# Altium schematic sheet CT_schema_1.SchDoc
size 849 x 820 mm
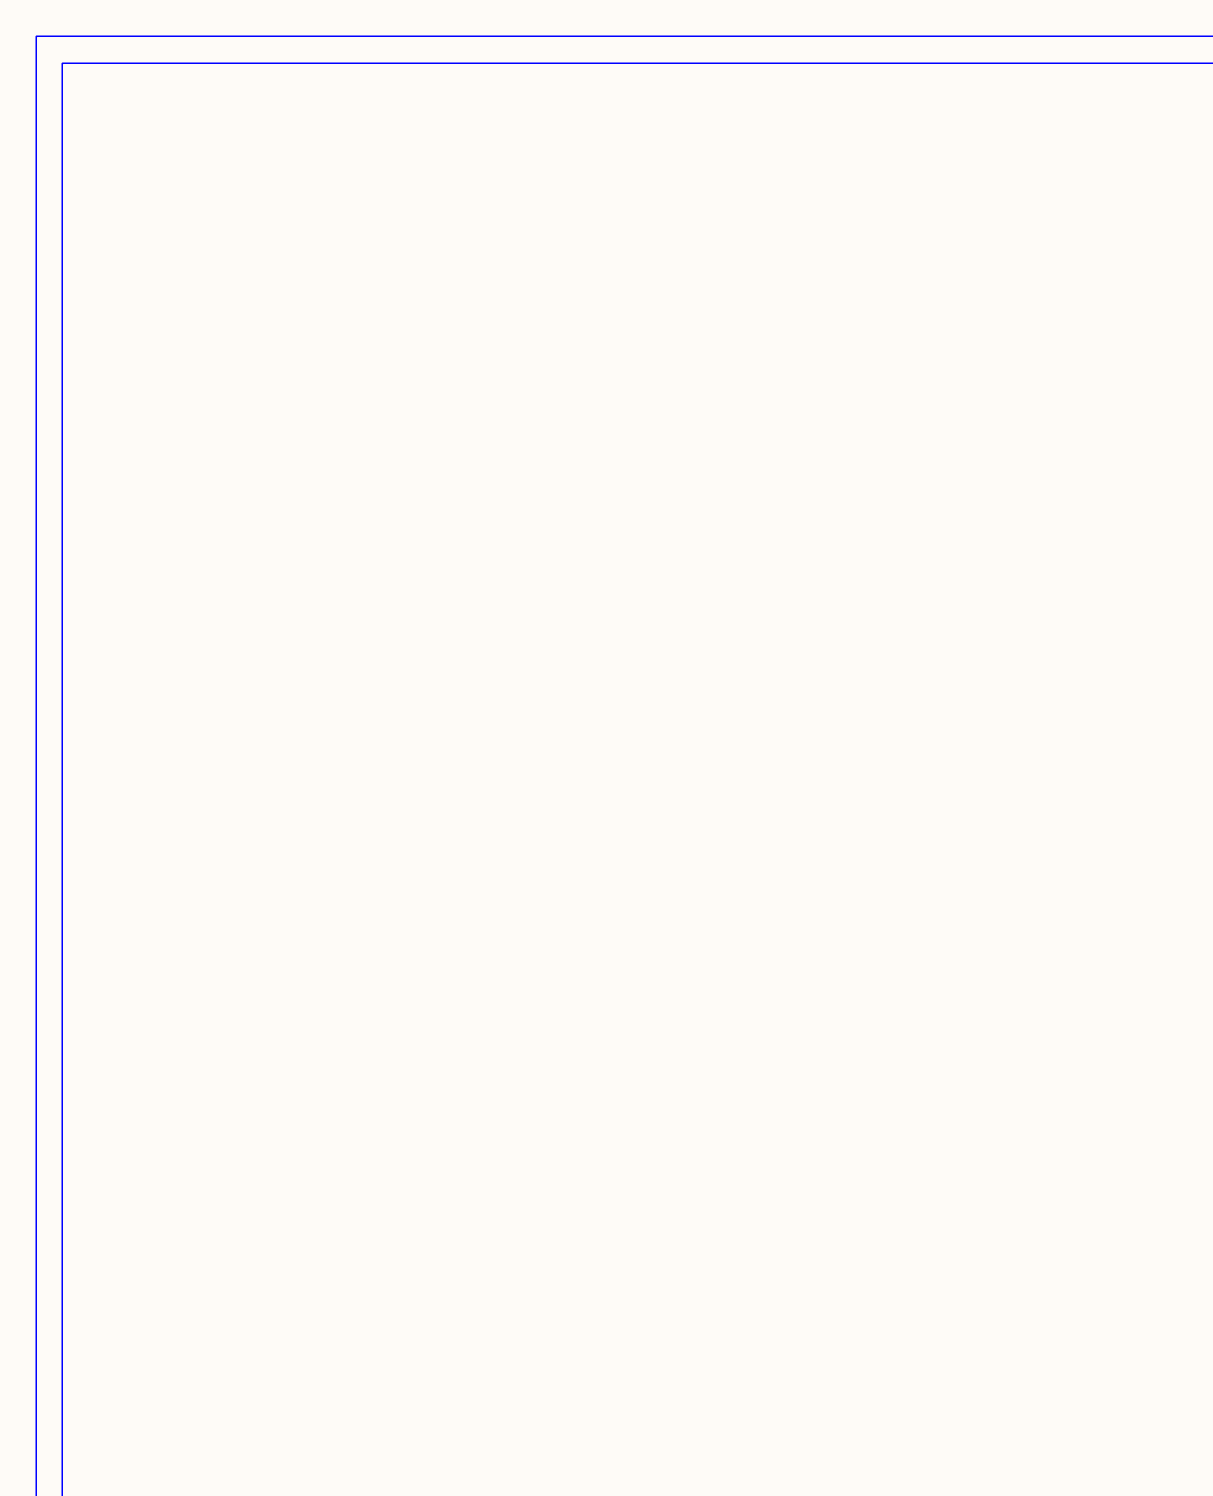
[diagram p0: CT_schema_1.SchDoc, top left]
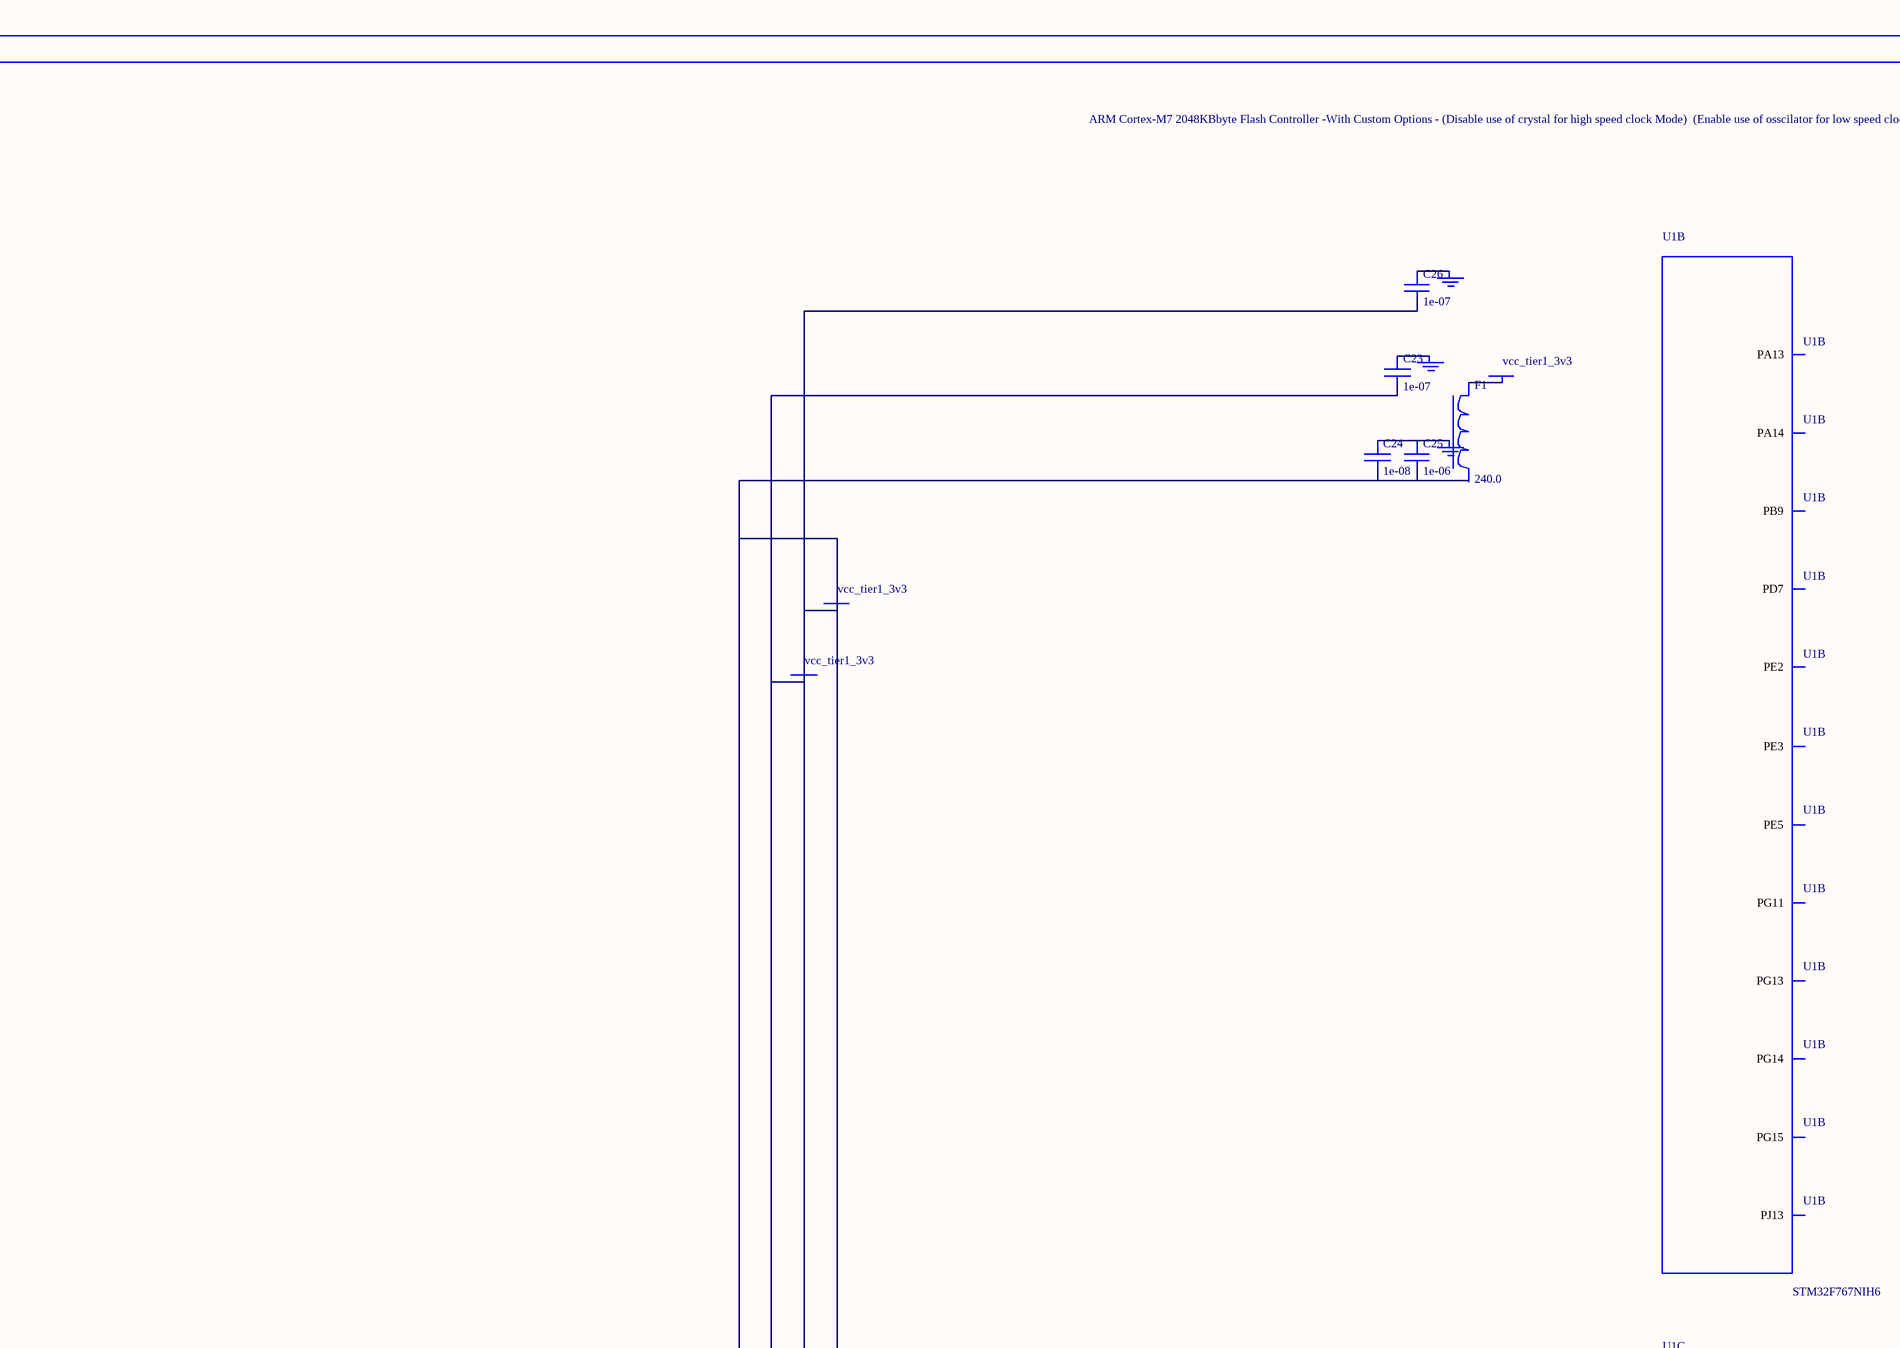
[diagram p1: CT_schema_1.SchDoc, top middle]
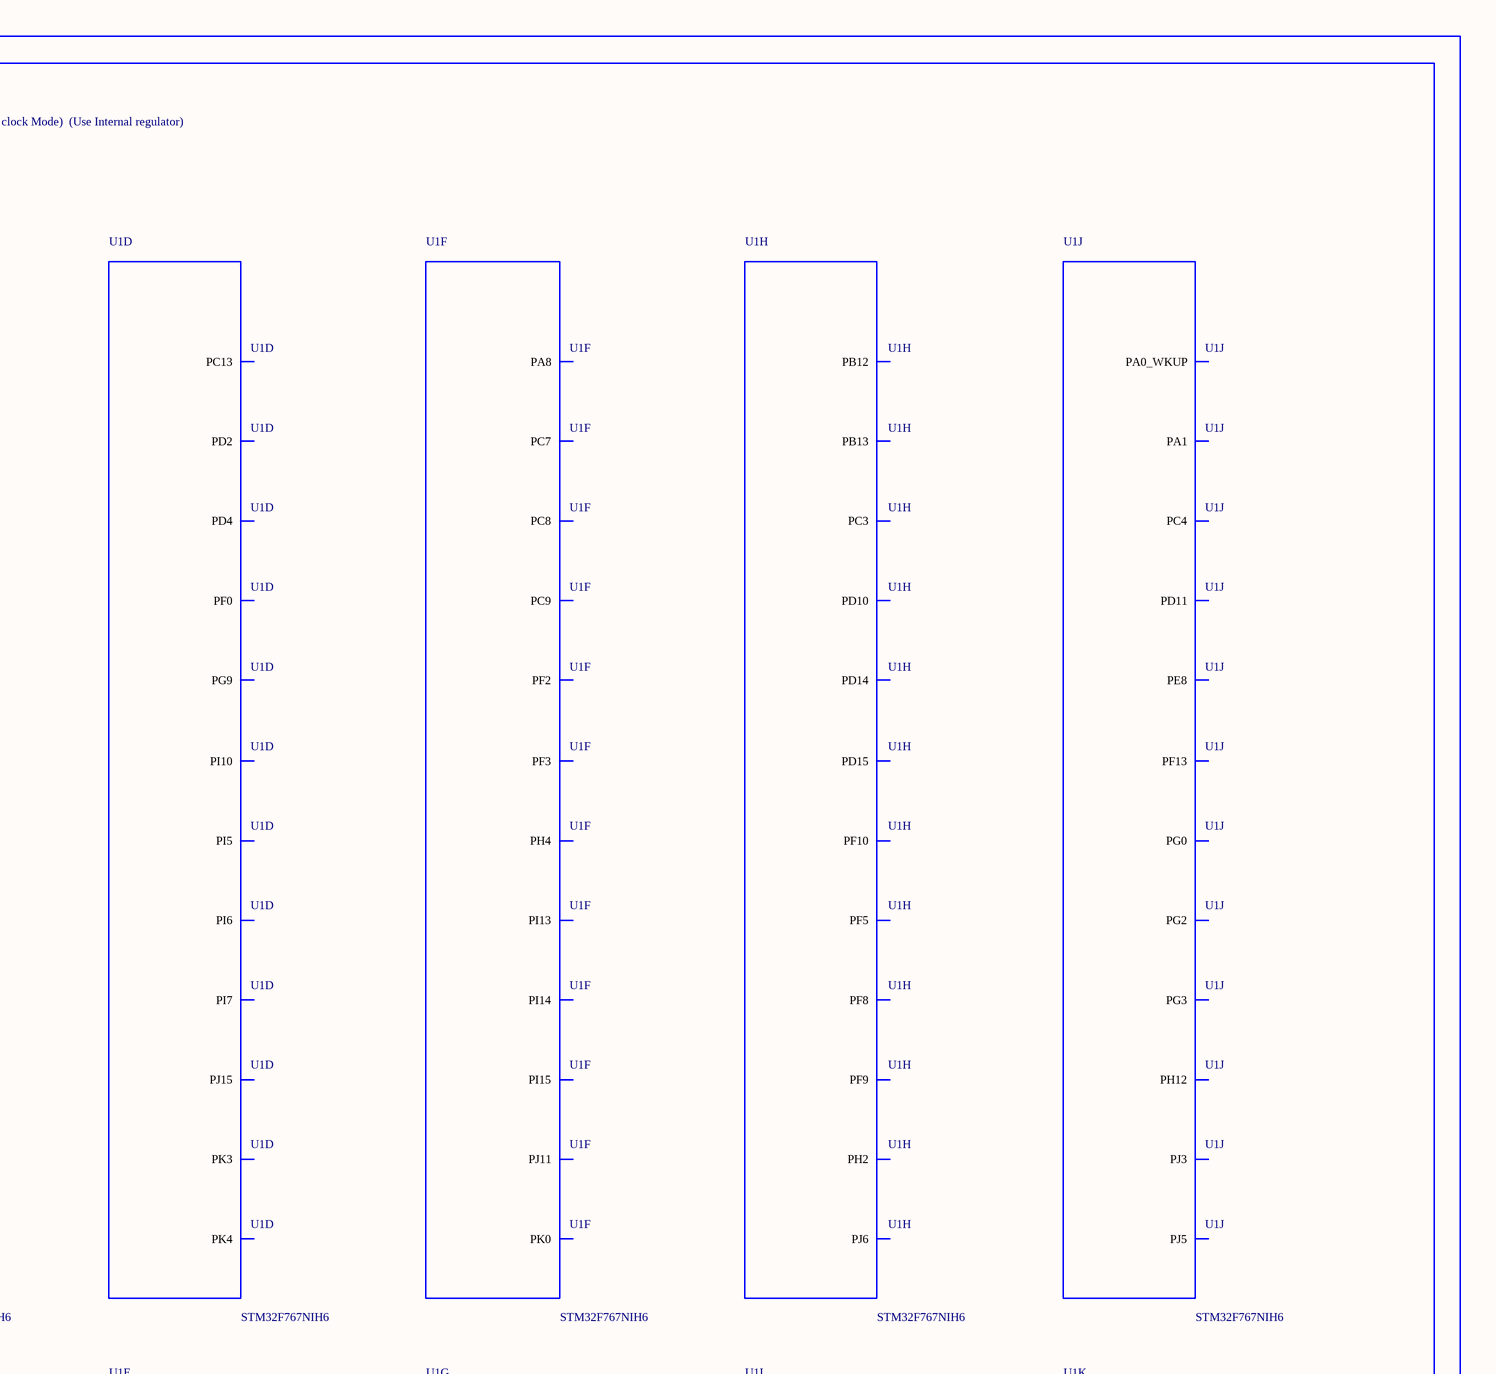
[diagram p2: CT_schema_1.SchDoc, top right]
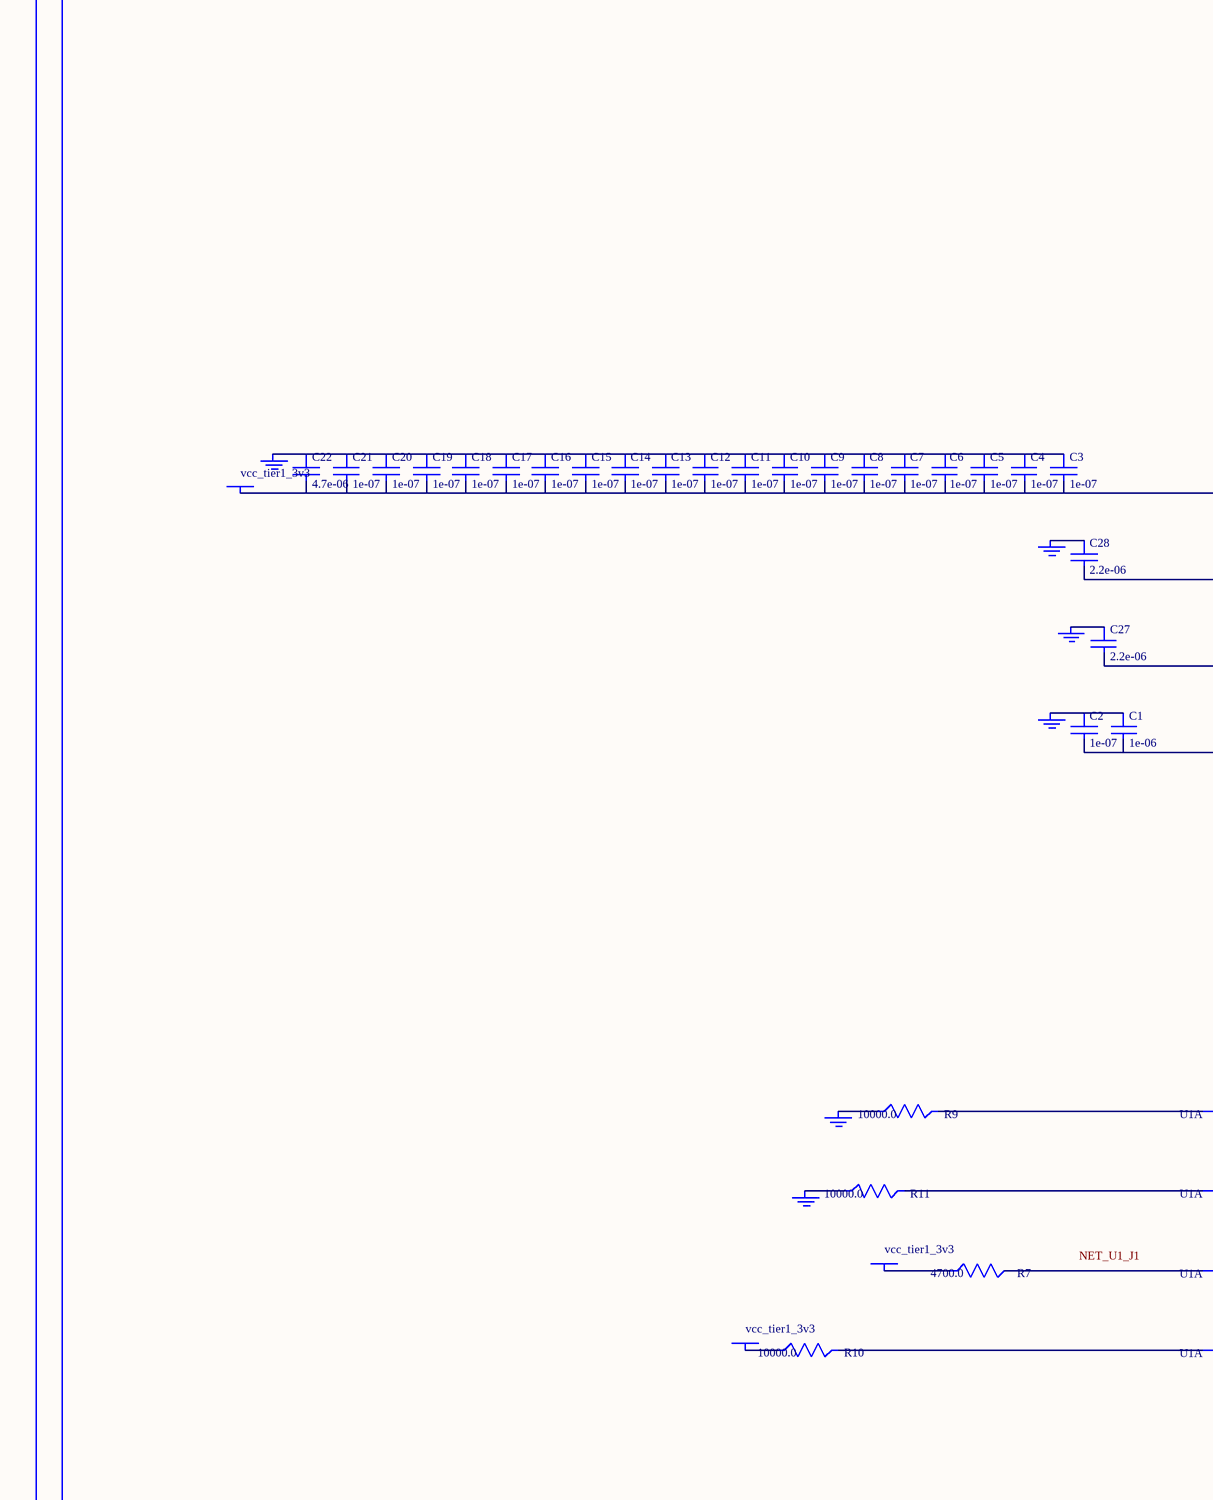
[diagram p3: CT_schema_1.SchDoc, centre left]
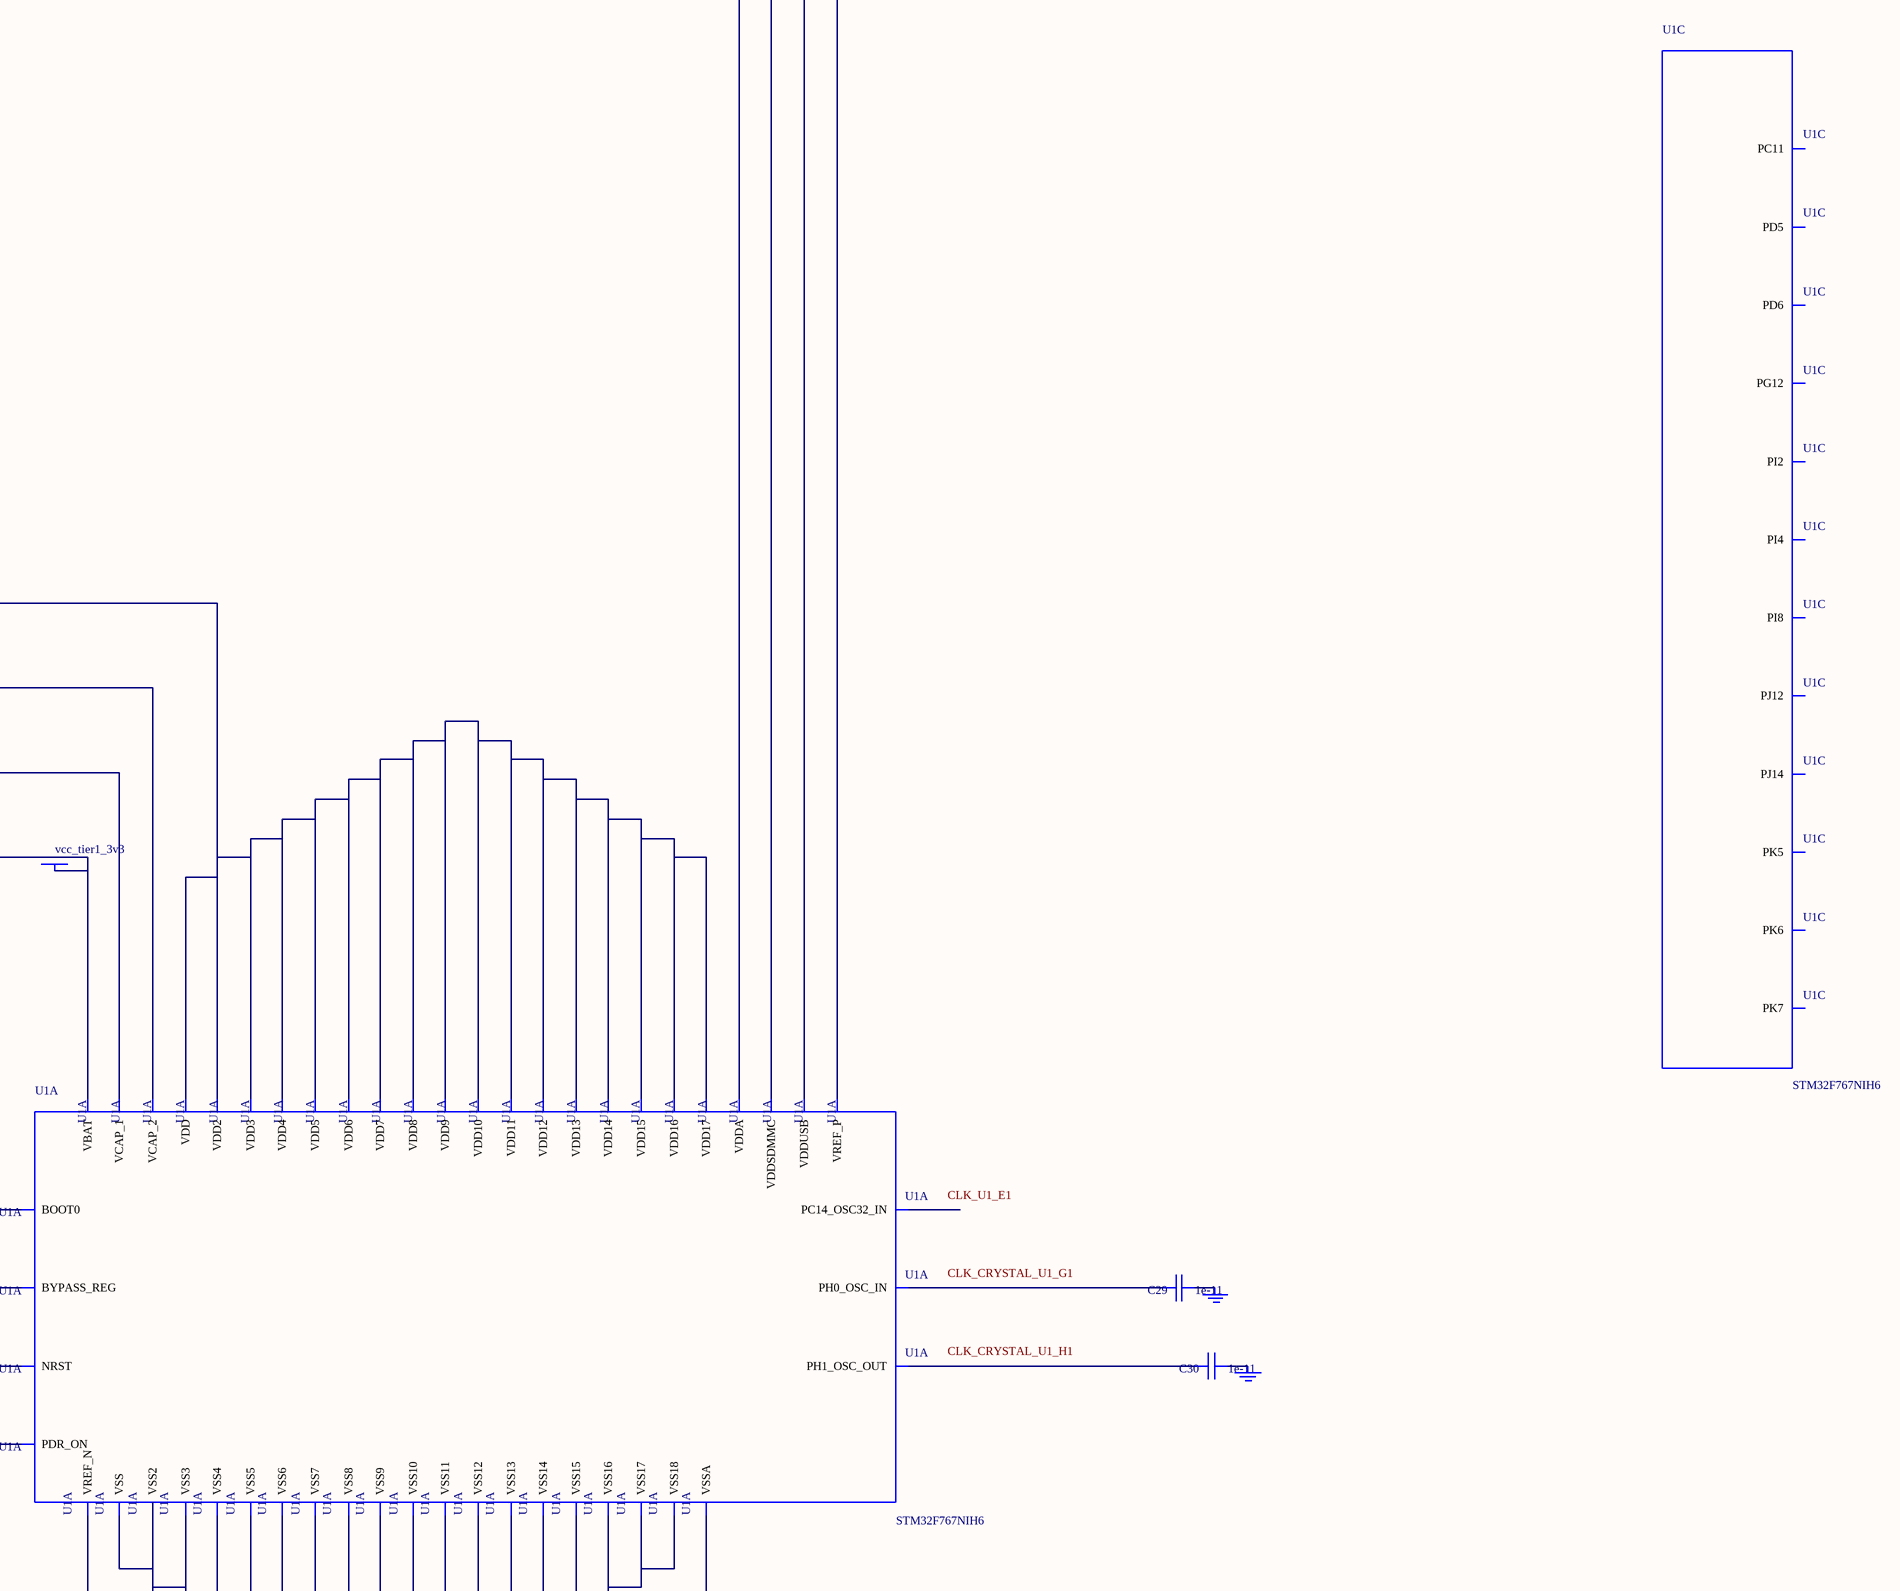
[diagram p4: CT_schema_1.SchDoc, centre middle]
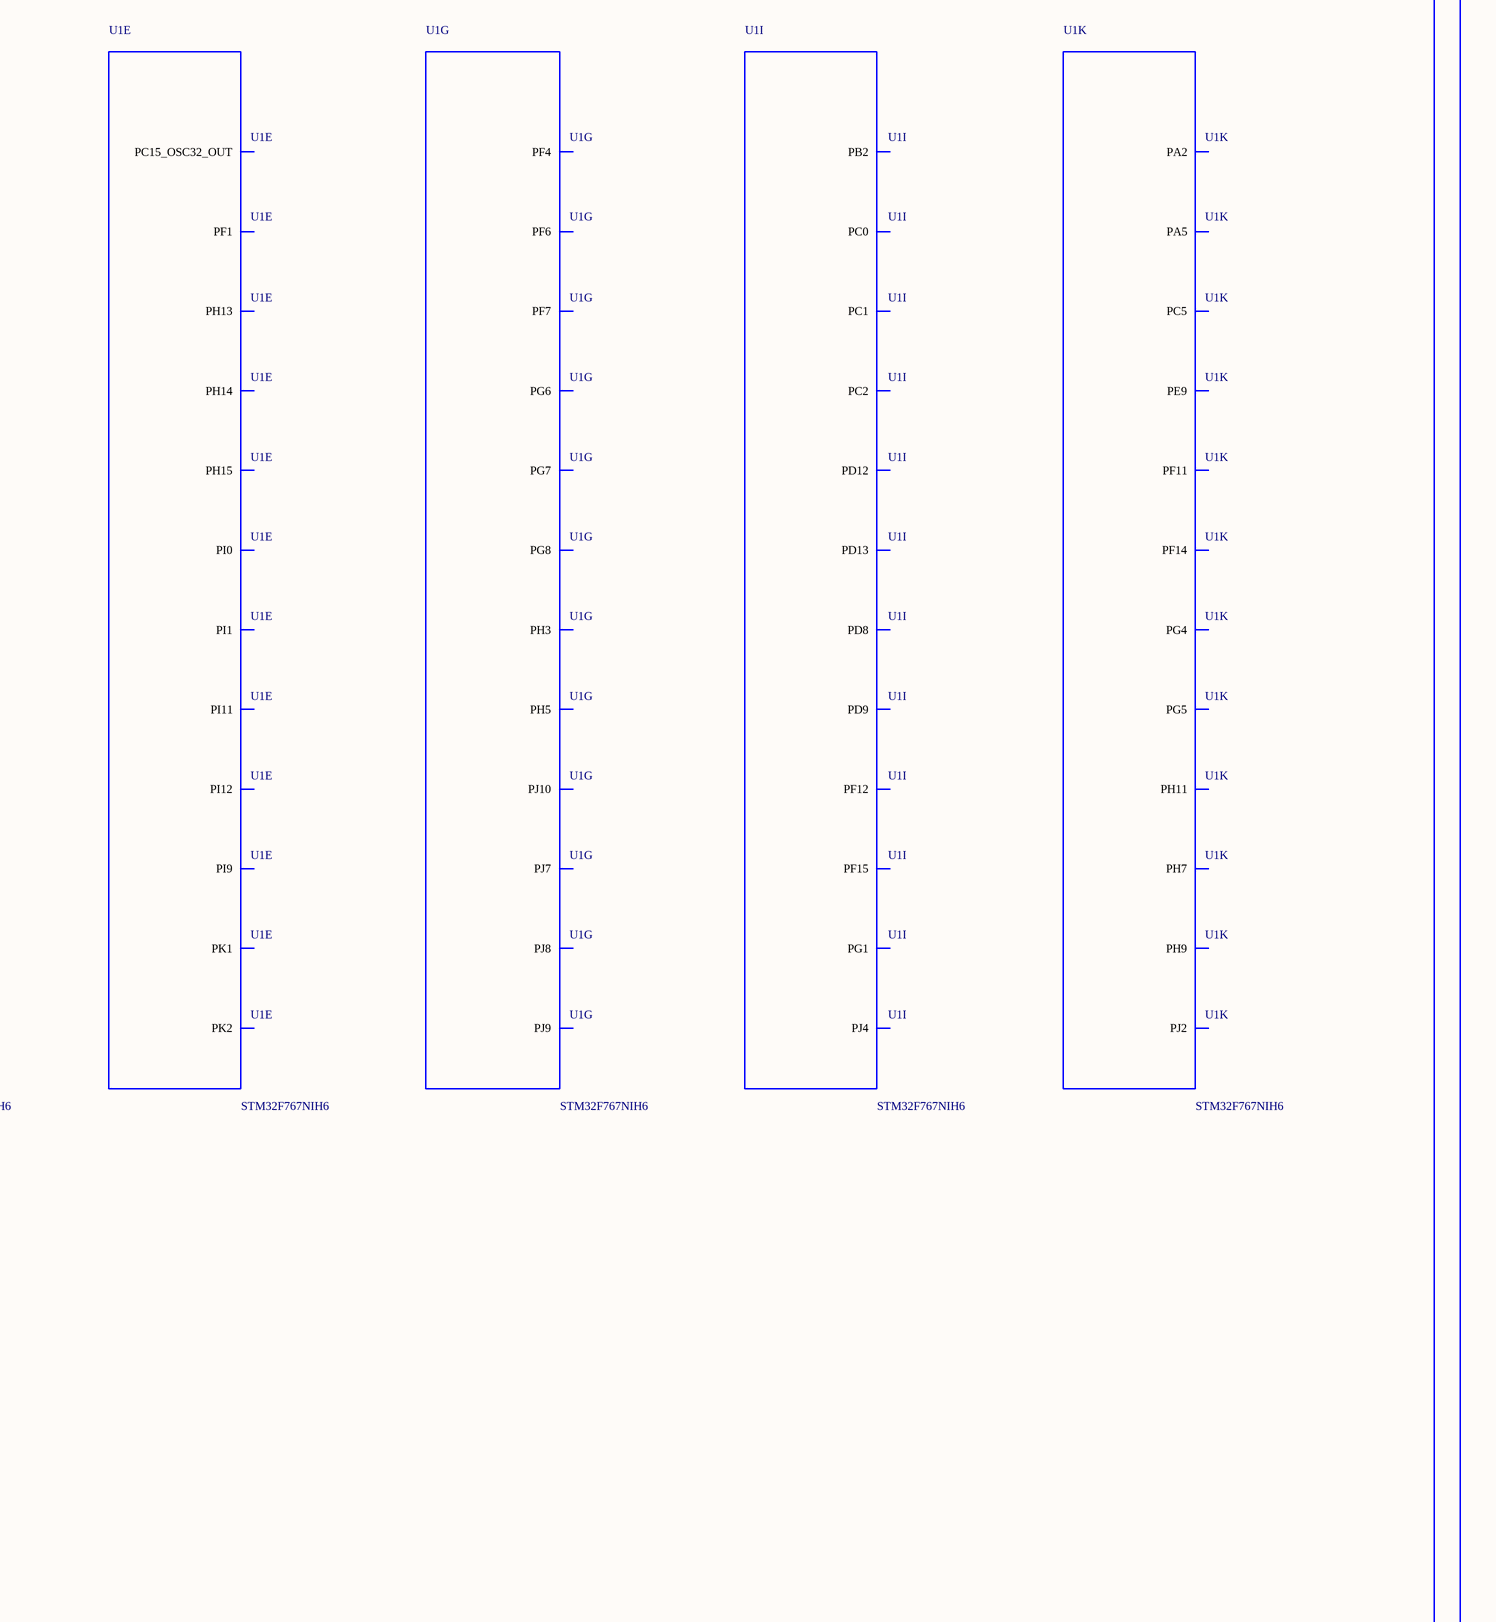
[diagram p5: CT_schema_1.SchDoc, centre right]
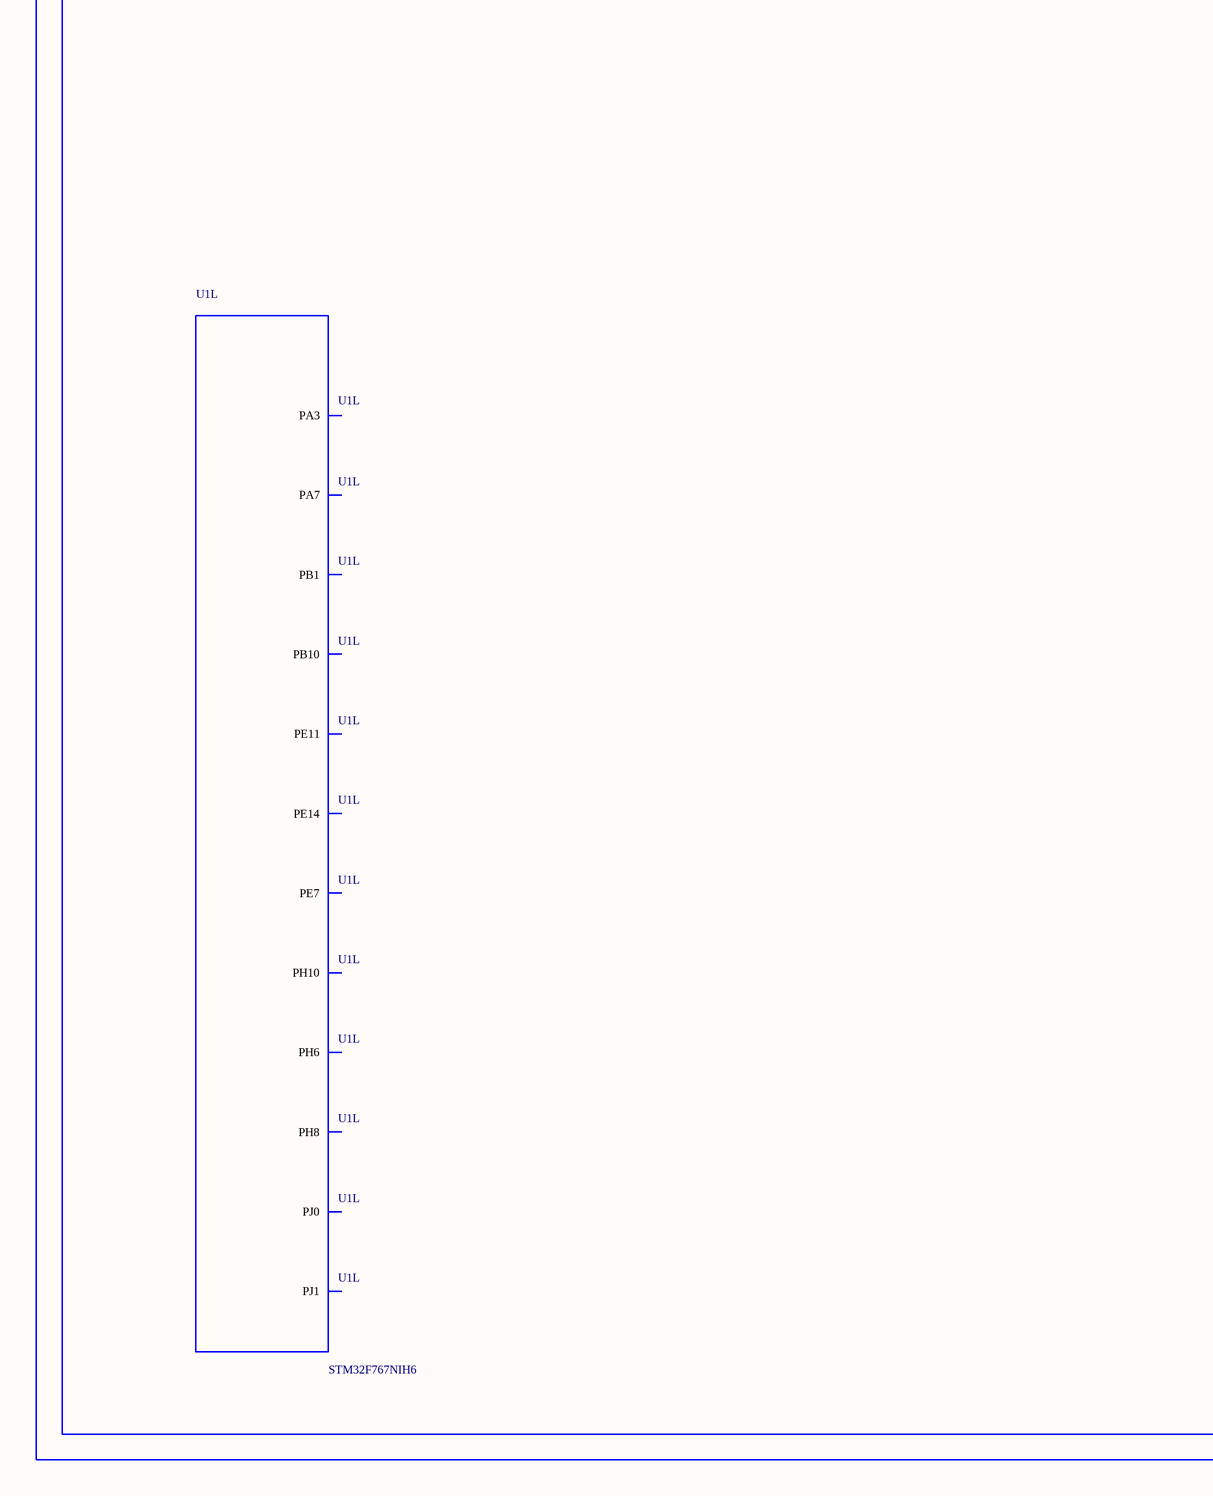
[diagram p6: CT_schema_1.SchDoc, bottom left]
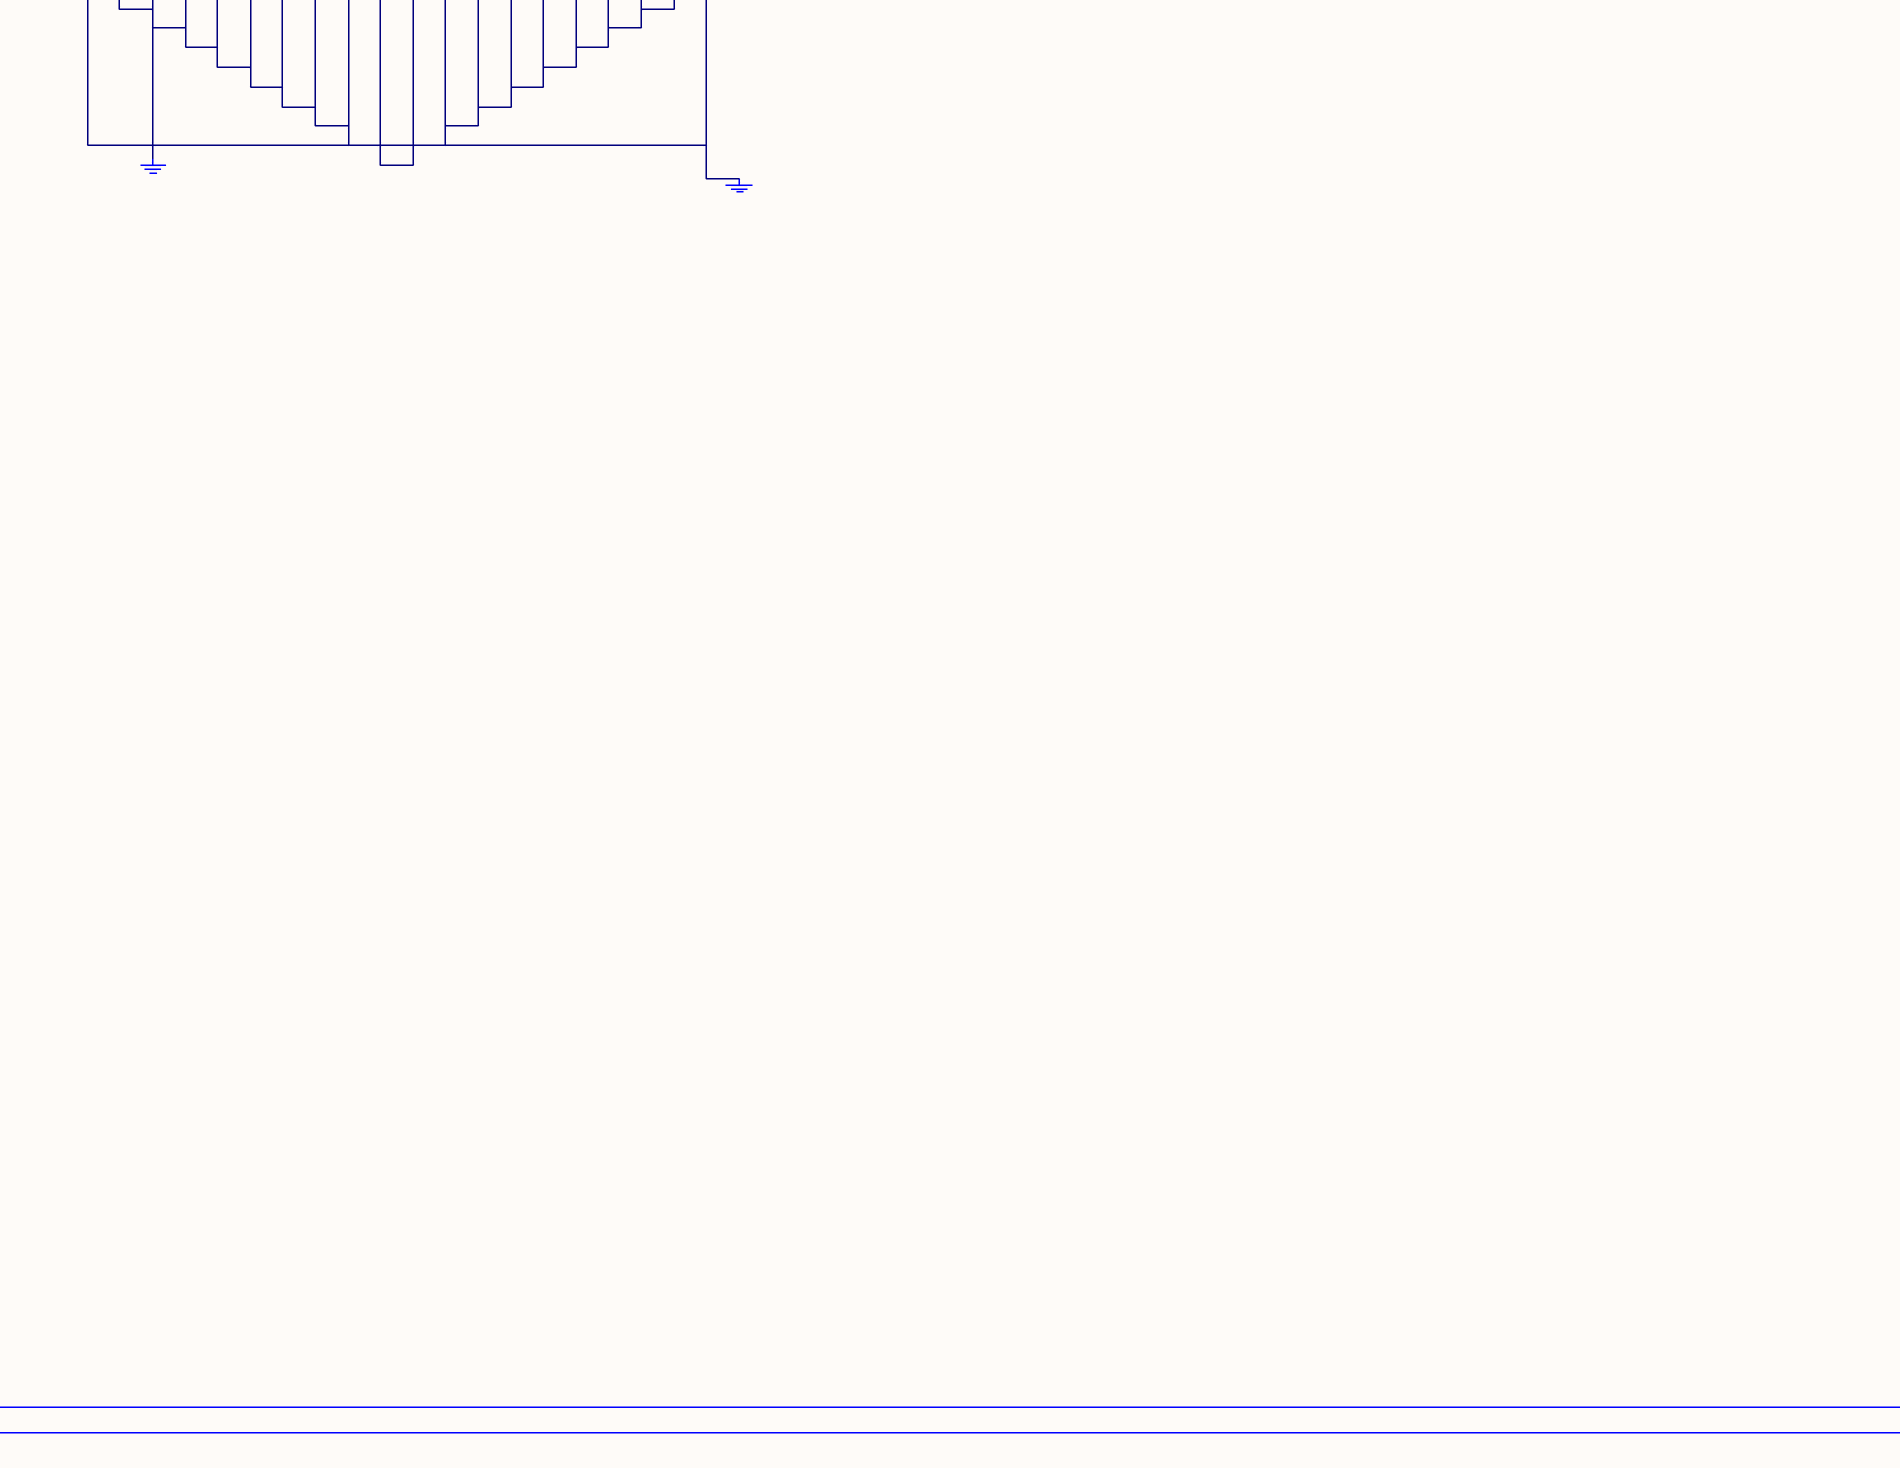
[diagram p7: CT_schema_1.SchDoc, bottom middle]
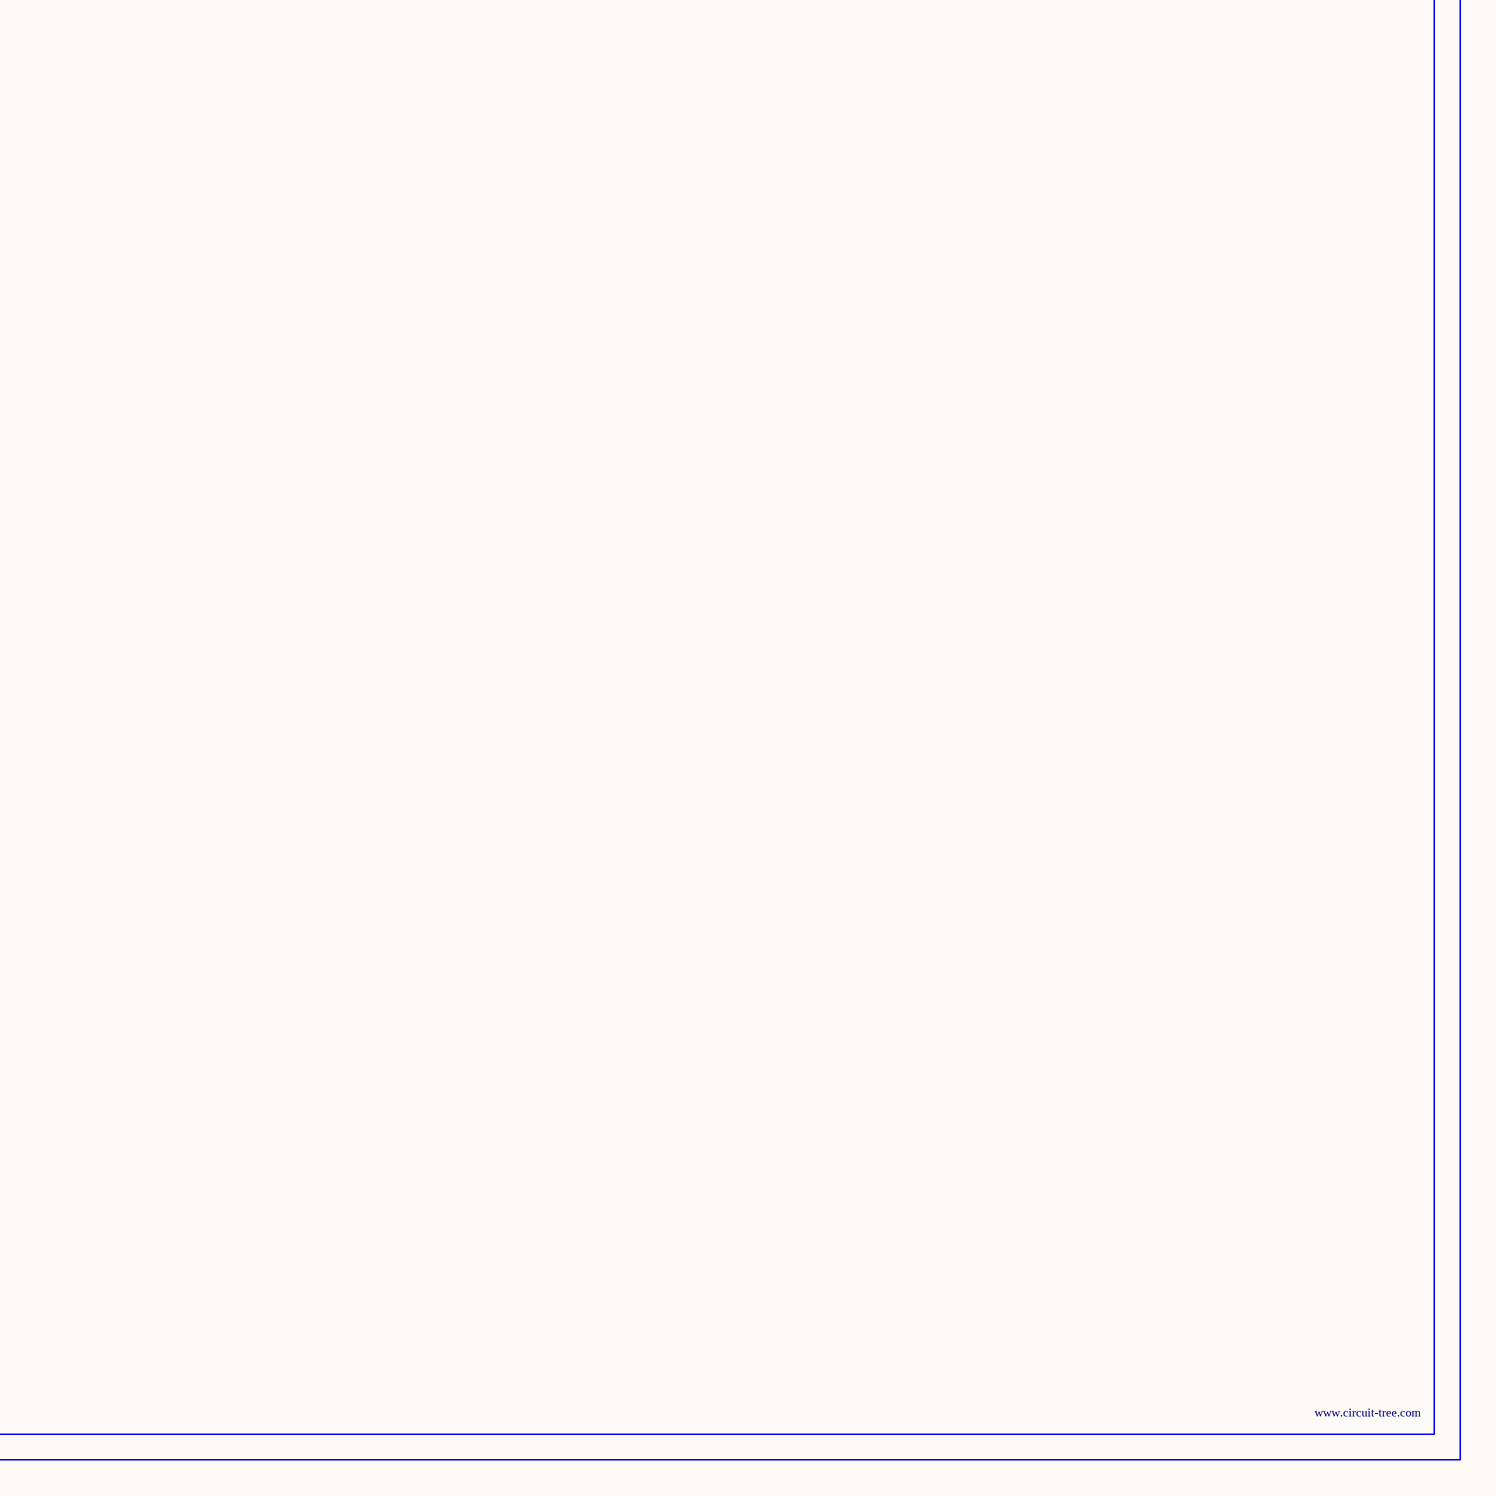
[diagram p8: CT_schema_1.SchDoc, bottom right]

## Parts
BORDER0  (no value)
C1  1e-06  [C0603]
C2  1e-07  [C0603]
C3  1e-07  [C0603]
C4  1e-07  [C0603]
C5  1e-07  [C0603]
C6  1e-07  [C0603]
C7  1e-07  [C0603]
C8  1e-07  [C0603]
C9  1e-07  [C0603]
C10  1e-07  [C0603]
C11  1e-07  [C0603]
C12  1e-07  [C0603]
C13  1e-07  [C0603]
C14  1e-07  [C0603]
C15  1e-07  [C0603]
C16  1e-07  [C0603]
C17  1e-07  [C0603]
C18  1e-07  [C0603]
C19  1e-07  [C0603]
C20  1e-07  [C0603]
C21  1e-07  [C0603]
C22  4.7e-06  [C0603]
C23  1e-07  [C0603]
C24  1e-08  [C0603]
C25  1e-06  [C0603]
C26  1e-07  [C0603]
C27  2.2e-06  [C0603]
C28  2.2e-06  [C0603]
C29  1e-11  [C0402]
C30  1e-11  [C0402]
F1  240.0  [L0603]
GND_INSTANCE_0_0  (no value)
GND_INSTANCE_0_1  (no value)
GND_INSTANCE_0_2  (no value)
GND_INSTANCE_0_3  (no value)
GND_INSTANCE_0_4  (no value)
GND_INSTANCE_0_5  (no value)
GND_INSTANCE_0_6  (no value)
GND_INSTANCE_0_7  (no value)
GND_INSTANCE_0_8  (no value)
GND_INSTANCE_0_9  (no value)
GND_INSTANCE_0_10  (no value)
GND_INSTANCE_0_11  (no value)
GND_INSTANCE_0_12  (no value)
POWER_INSTANCE_0_0  vcc_tier1_3v3
POWER_INSTANCE_0_1  vcc_tier1_3v3
POWER_INSTANCE_0_2  vcc_tier1_3v3
POWER_INSTANCE_0_3  vcc_tier1_3v3
POWER_INSTANCE_0_4  vcc_tier1_3v3
POWER_INSTANCE_0_5  vcc_tier1_3v3
POWER_INSTANCE_0_6  vcc_tier1_3v3
R7  4700.0  [R0603]
R9  10000.0  [R0603]
R10  10000.0  [R0603]
R11  10000.0  [R0603]
U1  STM32F767NIH6  [TFBGA216]  (parts A,B,C,D,E,F,G,H,I,J,K,L of 16)

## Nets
NetC1_1: C1.1 C2.1 GND_INSTANCE_0_0.0(GND)
NetC1_2: C1.2 C2.2 POWER_INSTANCE_0_0.0(PWR) U1.C1(VBAT)
NetC3_1: C3.1 C4.1 C5.1 C6.1 C7.1 C8.1 C9.1 C10.1 C11.1 C12.1 C13.1 C14.1 C15.1 C16.1 C17.1 C18.1 C19.1 C20.1 C21.1 C22.1 GND_INSTANCE_0_2.0(GND)
NetC3_2: C3.2 C4.2 C5.2 C6.2 C7.2 C8.2 C9.2 C10.2 C11.2 C12.2 C13.2 C14.2 C15.2 C16.2 C17.2 C18.2 C19.2 C20.2 C21.2 C22.2 POWER_INSTANCE_0_2.0(PWR) U1.E7(VDD2) U1.E8(VDD3) U1.E10(VDD) U1.F4(VDD5) U1.F5(VDD6) U1.F11(VDD4) U1.G5(VDD7) U1.H5(VDD9) U1.H11(VDD8) U1.J5(VDD11) U1.J11(VDD10) U1.K5(VDD13) U1.K11(VDD12) U1.L7(VDD15) U1.L8(VDD16) U1.L9(VDD17) U1.L10(VDD14)
NetC23_1: C23.1 GND_INSTANCE_0_4.0(GND)
NetC23_2: C23.2 C24.2 C25.2 C26.2 POWER_INSTANCE_0_3.0(PWR) POWER_INSTANCE_0_5.0(PWR) U1.E9(VDDSDMMC) U1.G11(VDDUSB) U1.P1(VREF_P) U1.R1(VDDA)
NetC24_1: C24.1 C25.1 GND_INSTANCE_0_1.0(GND)
NetC26_1: C26.1 GND_INSTANCE_0_5.0(GND)
NetC27_1: C27.1 GND_INSTANCE_0_7.0(GND)
NetC27_2: C27.2 U1.L11(VCAP_1)
NetC28_1: C28.1 GND_INSTANCE_0_8.0(GND)
NetC28_2: C28.2 U1.E11(VCAP_2)
NetC29_1: C29.1 GND_INSTANCE_0_9.0(GND)
NetC29_2: C29.2 U1.G1(PH0_OSC_IN)
NetC30_1: C30.1 GND_INSTANCE_0_10.0(GND)
NetC30_2: C30.2 U1.H1(PH1_OSC_OUT)
NetF1_1: F1.1 POWER_INSTANCE_0_1.0(PWR)
NetGND_INSTANCE_0_3_0: GND_INSTANCE_0_3.0(GND) R9.1
NetGND_INSTANCE_0_6_0: GND_INSTANCE_0_6.0(GND) R11.1
NetGND_INSTANCE_0_11_0: GND_INSTANCE_0_11.0(GND) GND_INSTANCE_0_12.0(GND) U1.F2(VSS2) U1.F6(VSS3) U1.F7(VSS4) U1.F8(VSS5) U1.F9(VSS6) U1.F10(VSS) U1.G6(VSS8) U1.G10(VSS7) U1.H6(VSS10) U1.H10(VSS9) U1.J6(VSS12) U1.J10(VSS11) U1.K6(VSS14) U1.K7(VSS15) U1.K8(VSS16) U1.K9(VSS17) U1.K10(VSS13) U1.L6(VSS18) U1.M1(VSSA) U1.N1(VREF_N)
NetPOWER_INSTANCE_0_4_0: POWER_INSTANCE_0_4.0(PWR) R10.1
NetPOWER_INSTANCE_0_6_0: POWER_INSTANCE_0_6.0(PWR) R7.1
NetR7_2: R7.2 U1.J1(NRST)
NetR9_2: R9.2 U1.E6(BOOT0)
NetR10_2: R10.2 U1.E5(PDR_ON)
NetR11_2: R11.2 U1.L5(BYPASS_REG)

Not connected (* = marked no-connect by the designer): F1 2; U1 A2(PE3) A3(PE2) A4(PG14) A11(PD7) A14(PA14) A15(PA13) B1(PE5) B3(PG13) B4(PB9) B7(PG15) B8(PG11) B9(PJ13) B10(PJ12) B11(PD6) B13(PC11) C2(PI8) C3(PI4) C4(PK7) C5(PK6) C6(PK5) C7(PG12) C9(PJ14) C10(PD5) C14(PI2) D1(PC13) D2(PF0) D3(PI5) D4(PI7) D5(PI10) D6(PI6) D7(PK4) D8(PK3) D9(PG9) D10(PJ15) D11(PD4) D12(PD2) D13(PH15) D14(PI1) E1(PC14_OSC32_IN) E2(PF1) E3(PI12) E4(PI9) E12(PH13) E13(PH14) E14(PI0) F1(PC15_OSC32_OUT) F3(PI11) F12(PK1) F13(PK2) F14(PC9) F15(PA8) G2(PF2) G3(PI13) G4(PI15) G12(PJ11) G13(PK0) G14(PC8) G15(PC7) H2(PF3) H3(PI14) H4(PH4) H12(PJ8) H13(PJ10) H14(PG8) J2(PF4) J3(PH5) J4(PH3) J12(PJ7) J13(PJ9) J14(PG7) J15(PG6) K1(PF7) K2(PF6) K3(PF5) K4(PH2) K12(PJ6) K13(PD15) K14(PB13) K15(PD10) L1(PF10) L2(PF9) L3(PF8) L4(PC3) L12(PD14) L13(PB12) L14(PD9) L15(PD8) M2(PC0) M3(PC1) M4(PC2) M5(PB2) M6(PF12) M7(PG1) M8(PF15) M9(PJ4) M10(PD12) M11(PD13) M12(PG3) M13(PG2) M14(PJ5) M15(PH12) N2(PA1) N3(PA0_WKUP) N5(PC4) N6(PF13) N7(PG0) N8(PJ3) N9(PE8) N10(PD11) N11(PG5) N12(PG4) N13(PH7) N14(PH9) N15(PH11) P2(PA2) P4(PA5) P5(PC5) P6(PF14) P7(PJ2) P8(PF11) P9(PE9) P10(PE11) P11(PE14) P12(PB10) P13(PH6) P14(PH8) P15(PH10) R2(PA3) R3(PA7) R4(PB1) R6(PJ0) R7(PJ1) R8(PE7)

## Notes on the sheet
- Labels drawn without touching a wire or pin: CLK_CRYSTAL_U1_G1, CLK_CRYSTAL_U1_H1, CLK_U1_E1, NET_U1_J1

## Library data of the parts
BORDER0 = BORDER_PAGE0
C1 C25 = C0603C105K3RACTU
C2-C21 C23 C26 = 06035C104K4Z2A
C22 = GRM188R6YA475KE15D
C24 = 06035C103K4Z2A
C27 C28 = C0603C225K8RACTU
C29 C30 = C0402C100K3GACTU
F1 = Z0603C241ASMST
GND_INSTANCE_0_0-GND_INSTANCE_0_12 = GND
POWER_INSTANCE_0_0-POWER_INSTANCE_0_6 = PWR
R7 = RC0603JR-074K7L
R9-R11 = RC0603JR-0710KL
